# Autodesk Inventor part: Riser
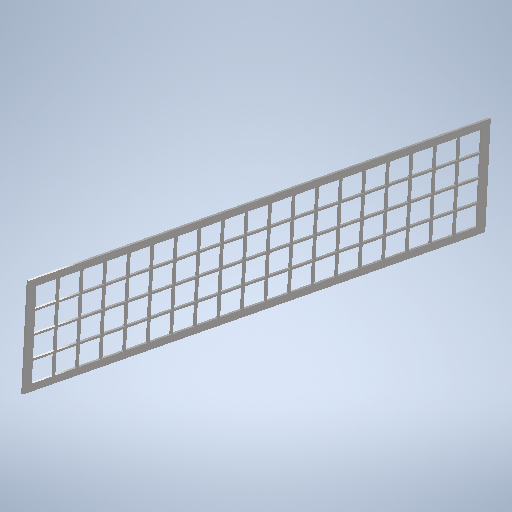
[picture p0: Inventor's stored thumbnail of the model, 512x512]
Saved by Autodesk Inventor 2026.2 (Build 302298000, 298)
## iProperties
RuleStatus: InUse
AfterAnyParamChange0: pattern base location
AfterAnyUserParamChange0: pattern base location
Created: 2022-06
Part Number: Riser
Material: Steel, Galvanized
Document SubType Name: Modeling
Designer: reaumed
Density: 7.85 g/cm^3
Appearance: Galvanized
Mass: 845.798 g
Surface Area: 1112.5 cm^2
Volume: 107.745 cm^3
Author: reaumed
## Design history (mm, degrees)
workplane "Work Plane1"
sketch "Sketch1"
  geometry: L1 (-342.9, -222.25)-(342.9, -222.25); L2 (342.9, -222.25)-(342.9, -381); L3 (342.9, -381)-(-342.9, -381); L4 (-342.9, -381)-(-342.9, -222.25); 3 further points
  constraints: 8 end point, 2 parallel, 1 coincident, 1 horizontal, 1 midpoint, 1 perpendicular
  dimensions: "ActualRiserWidth" = 685.8 distance of L2.end L3.end (= Width - 2 x StringerThickness); "ActualRiserHeight" = 158.75 distance of L1.end L2.end (= Rise - TreadThickness); "d5" = 222.25 distance from line of L1 point (0, 0) (= Rise + TreadThickness); "d6" = 0 horizontal distance of point (0, 0) point (0, -222.25)
extrude "Extrusion1" new body sketch "Sketch1" distance "d3" = 3.175 (= RiserThickness); taper "d4" = 0 deg
sketch "Sketch2"
  geometry: L1 (233.362, -330.2)-(265.112, -330.2); L2 (265.112, -330.2)-(265.112, -298.45); L3 (265.112, -298.45)-(233.362, -298.45); L4 (233.362, -298.45)-(233.362, -330.2); L5 (233.362, -330.2)-(265.112, -298.45); L6 (381, -342.9)-(381, 342.9) reference; L7 (381, 342.9)-(222.25, 342.9) reference; L8 (381, -342.9)-(222.25, 342.9); 3 further points
  constraints: 12 end point, 2 midpoint, 2 parallel, 1 horizontal, 1 perpendicular
  dimensions: "d7" = 31.75 distance of L2.end L3.end (= HoleSize); "HoleSize" = 31.75 distance of L3.end L1.start; "x_loc" = 314.325 vertical distance of point (249.237, -314.325) point (0, 0); "y_loc" = 52.3875 horizontal distance of point (301.625, 0) point (249.237, -314.325)
extrude "Grating Extrusion" cut sketch "Sketch2" extent not by distance; stored distance "d12" = 0; taper "d13" = 0 deg
body "Solid1"
pattern_linear "Grating Pattern" dims "d16" = 34.925 (= HoleSize + HoleSpacing), "d19" = 34.925 (= HoleSize + HoleSpacing)
other parameters: "Run" = 228.6 [user parameter; used in 1 equation term], "Width" = 762 [user parameter; used in 1 equation term], "Rise" = 190.5 [user parameter; used in 2 equation terms], "TreadThickness" = 31.75 [user parameter; used in 2 equation terms], "RiserThickness" = 3.175 [user parameter; used in 1 equation term], "d0" = 228.6 (= Run), "StringerThickness" = 38.1 [user parameter; used in 1 equation term], "HoleSpacing" = 3.175 [user parameter; used in 2 equation terms]
